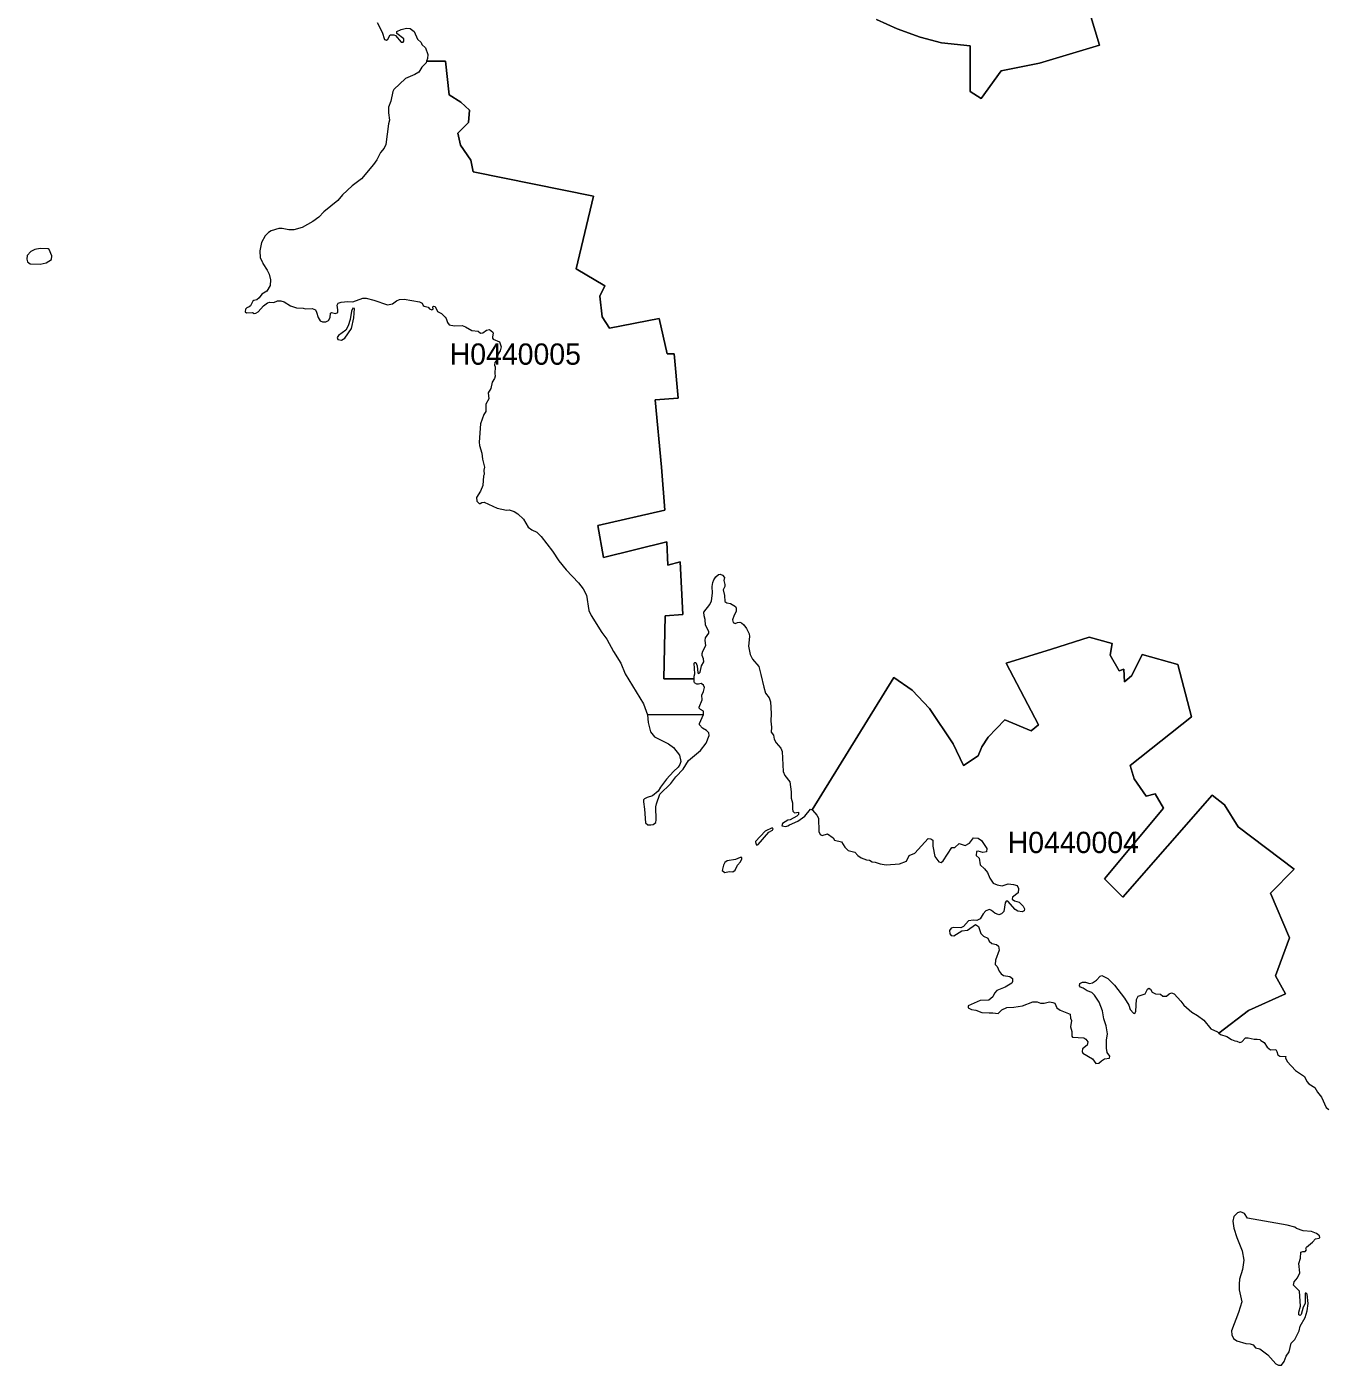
# Model space of a CAD drawing. Extents: x 369010 to 739155, y 6377141 to 6616555.
# Drawn here: x 371724 to 377844, y 6457015 to 6463309 of the extents above; entities that cross this region are included whole.
import ezdxf
from ezdxf.enums import TextEntityAlignment as Align

# ---------------------------------------------------------------- set-up
doc = ezdxf.new("R2010")
doc.units = 0
doc.header["$LTSCALE"] = 40
doc.layers.add('1', color=7, linetype='Continuous', lineweight=13)
doc.layers.add('2', color=7, linetype='Continuous')

msp = doc.modelspace()

# ---------------------------------------------------------------- linework, layer by layer
at = {"layer": '1'}
for points in [[(375720.07, 6463343.08), (375816.39, 6463298.89), (375925.13, 6463259.01), (376025.26, 6463232.53), (376160.97, 6463218.29), (376160.97, 6463004.3), (376211.95, 6462970.7), (376306.28, 6463101.61), (376486.85, 6463137.03), (376767.88, 6463221.93), (376686.94, 6463493.36)], [(376686.94, 6463493.36), (376767.88, 6463221.93), (376486.85, 6463137.03), (376306.28, 6463101.61), (376211.95, 6462970.7), (376160.97, 6463004.3), (376160.97, 6463218.29), (376025.26, 6463232.53), (375925.13, 6463259.01), (375816.39, 6463298.89), (375720.07, 6463343.08)], [(373372.23, 6463328.68), (373395.07, 6463282.51), (373406.65, 6463248.08), (373415.59, 6463246.43), (373421.88, 6463250.4), (373433.14, 6463270.92), (373450.18, 6463271.25), (373458.13, 6463266.95), (373483.95, 6463235.84), (373494.37, 6463235.51), (373496.52, 6463240.8), (373497.85, 6463252.06), (373464.08, 6463276.88), (373464.08, 6463285.82), (373484.61, 6463295.42), (373510.43, 6463301.54), (373527.47, 6463300.05), (373545.68, 6463287.14), (373561.9, 6463249.74), (373578.78, 6463234.51), (373582.42, 6463224.58), (373598.64, 6463209.19), (373609.4, 6463178.74), (373608.4, 6463160.2), (373604.27, 6463147.62), (373693.8, 6463147.13), (373710.69, 6462988.41), (373765.3, 6462954.81), (373806.68, 6462916.58), (373801.05, 6462858.16), (373751.9, 6462808.67), (373763.32, 6462752.07), (373812.31, 6462681.23), (373823.56, 6462626.45), (374389.58, 6462511.43), (374307.99, 6462170.65), (374441.88, 6462091.05), (374419.21, 6462041.56), (374430.63, 6461944.24), (374464.56, 6461891.12), (374698.41, 6461937.13), (374736.15, 6461770.8), (374768.26, 6461770.8), (374787.12, 6461562.09), (374679.55, 6461554.98), (374709.67, 6461237.54), (374724.89, 6461035.96), (374409.77, 6460963.3), (374436.26, 6460813.02), (374734.33, 6460887.33), (374737.97, 6460777.61), (374796.72, 6460792.34), (374809.3, 6460544.74), (374726.88, 6460538.45), (374719.27, 6460242.86), (374861.77, 6460242.2), (374861.77, 6460255.27), (374865.41, 6460265.21), (374862.76, 6460315.68), (374866.07, 6460319.66)], [(373604.27, 6463147.62), (373601.62, 6463139.35), (373581.76, 6463118.66), (373568.19, 6463094.83), (373548.66, 6463083.57), (373505.79, 6463064.71), (373450.84, 6463013.56), (373446.21, 6463004.3), (373435.45, 6462958.12), (373425.85, 6462930.32), (373425.19, 6462903.17), (373429.16, 6462868.91), (373425.19, 6462851.7), (373413.28, 6462755.71), (373405, 6462738), (373387.46, 6462717.31), (373370.58, 6462683.55), (373355.18, 6462661.04), (373298.91, 6462593.35), (373255.05, 6462560.41), (373209.04, 6462518.71), (373187.36, 6462492.23), (373121.16, 6462438.77), (373097.49, 6462413.28), (373068.7, 6462392.76), (373019.87, 6462365.45), (372980.48, 6462354.2), (372956.65, 6462354.2), (372925.04, 6462360.15), (372909.15, 6462360.82), (372872.74, 6462349.23), (372860.33, 6462340.79), (372845.43, 6462326.23), (372827.56, 6462294.12), (372819.61, 6462255.72), (372821.27, 6462221.46), (372832.52, 6462201.93), (372833.51, 6462195.64), (372854.7, 6462164.2), (372864.63, 6462145), (372870.09, 6462118.02), (372867.94, 6462092.53), (372852.71, 6462065.23), (372829.87, 6462050.66), (372816.96, 6462034.11), (372806.04, 6462025.17), (372791.81, 6462022.2), (372787.5, 6462018.89), (372775.75, 6461996.71), (372770.46, 6461991.58), (372758.87, 6461986.61), (372752.58, 6461980.32), (372751.59, 6461967.74), (372757.22, 6461964.1), (372785.35, 6461965.1), (372793.13, 6461960.79), (372801.41, 6461961.46), (372812.33, 6461968.74), (372837.16, 6461995.72), (372856.35, 6462009.95), (372867.11, 6462014.25), (372886.64, 6462011.6), (372902.53, 6462019.22), (372918.42, 6462019.22), (372934.64, 6462015.91), (372964.59, 6461995.72), (372992.73, 6461986.94), (373024.51, 6461985.95), (373034.6, 6461982.64), (373066.38, 6461983.3), (373081.61, 6461977.01), (373087.23, 6461967.08), (373094.51, 6461940.93), (373104.44, 6461926.37), (373114.54, 6461921.4), (373130.43, 6461920.41), (373143.01, 6461927.69), (373151.61, 6461941.26), (373152.94, 6461962.45), (373156.58, 6461965.76), (373176.44, 6461959.8), (373186.37, 6461965.43), (373187.03, 6461977.68), (373183.06, 6461999.36), (373188.69, 6462008.62), (373202.42, 6462013.59), (373234.2, 6462016.24), (373258.03, 6462014.91), (373304.87, 6462032.13), (373319.43, 6462031.79), (373355.68, 6462023.19), (373420.23, 6462001.67), (373444.56, 6462006.31), (373462.1, 6462019.55), (373476.66, 6462025.51), (373498.51, 6462027.82), (373571.17, 6462014.58), (373583.41, 6462008.62), (373587.39, 6461997.37), (373593.01, 6461994.06)], [(374883.28, 6460216.55), (374875.01, 6460216.55), (374864.75, 6460223.17), (374861.77, 6460229.13), (374861.77, 6460242.2), (374719.27, 6460242.86), (374726.88, 6460538.45), (374809.3, 6460544.74), (374796.72, 6460792.34), (374737.97, 6460777.61), (374734.33, 6460887.33), (374436.26, 6460813.02), (374409.77, 6460963.3), (374724.89, 6461035.96), (374709.67, 6461237.54), (374679.55, 6461554.98), (374787.12, 6461562.09), (374768.26, 6461770.8), (374736.15, 6461770.8), (374698.41, 6461937.13), (374464.56, 6461891.12), (374430.63, 6461944.24), (374419.21, 6462041.56), (374441.88, 6462091.05), (374307.99, 6462170.65), (374389.58, 6462511.43), (373823.56, 6462626.45), (373812.31, 6462681.23), (373763.32, 6462752.07), (373751.9, 6462808.67), (373801.05, 6462858.16), (373806.68, 6462916.58), (373765.3, 6462954.81), (373710.69, 6462988.41), (373693.8, 6463147.13), (373604.27, 6463147.62)], [(373593.01, 6461994.06), (373612.38, 6461990.42), (373618.33, 6461982.31), (373628.6, 6461977.68), (373634.88, 6461980.32), (373633.89, 6461991.74), (373636.54, 6461994.06), (373645.15, 6461993.4), (373655.41, 6461969.4), (373673.61, 6461960.79), (373691.98, 6461943.58), (373696.62, 6461936.63), (373702.25, 6461918.42), (373711.18, 6461907.34), (373735.01, 6461902.37), (373771.26, 6461904.36), (373787.81, 6461898.4), (373817.6, 6461880.86), (373847.06, 6461877.55), (373857.49, 6461868.28), (373868.41, 6461868.94), (373886.29, 6461881.85), (373900.52, 6461885.16), (373916.08, 6461872.25), (373918.06, 6461867.61), (373913.76, 6461851.4), (373914.42, 6461843.78), (373917.4, 6461839.81), (373947.36, 6461826.74), (373954.97, 6461803.23), (373950.67, 6461785.03), (373939.74, 6461767.49), (373935.44, 6461744.81), (373925.34, 6461729.92), (373923.69, 6461717.01), (373926.67, 6461709.39), (373925.68, 6461677.62), (373927.33, 6461665.04), (373924.02, 6461653.95), (373912.77, 6461637.4), (373906.81, 6461607.28), (373894.56, 6461587.75), (373896.88, 6461559.12), (373882.64, 6461533.3), (373882.31, 6461499.7), (373873.71, 6461485.47), (373857.16, 6461441.77), (373850.87, 6461354.55), (373852.85, 6461339.99), (373864.77, 6461303.74), (373866.43, 6461274.61), (373876.69, 6461238.37), (373873.05, 6461223.8), (373875.69, 6461203.28), (373871.39, 6461196.99), (373868.74, 6461151.15), (373857.82, 6461124.34), (373839.45, 6461095.21), (373840.77, 6461077.83), (373850.87, 6461067.24), (373856.49, 6461067.24), (373863.45, 6461072.2), (373875.03, 6461072.86), (373936.43, 6461045.39), (373980.13, 6461035.79), (373992.04, 6461036.45), (374016.37, 6461028.51), (374033.25, 6461018.25), (374060.73, 6460993.26), (374081.25, 6460955.19), (374098.63, 6460942.28), (374122.13, 6460932.35), (374142.98, 6460911.33), (374196.11, 6460843.31), (374225.57, 6460797.96), (374261.15, 6460755.1), (374319.08, 6460693.86), (374340.1, 6460664.9), (374356.65, 6460635.11), (374367.9, 6460563.77), (374377.83, 6460539.94), (374427.98, 6460460.67), (374451.15, 6460428.39), (374483.26, 6460371.46), (374518.18, 6460315.35), (374538.7, 6460265.87), (374624.93, 6460124.36), (374642.47, 6460073.55), (374907.11, 6460074.21), (374906.12, 6460090.76), (374892.88, 6460097.72), (374886.59, 6460104.67), (374886.59, 6460109.3), (374900.49, 6460143.56), (374898.51, 6460165.41), (374907.11, 6460183.28), (374911.25, 6460201.65), (374907.11, 6460212.24), (374895.2, 6460220.52), (374883.28, 6460216.55)], [(374866.07, 6460319.66), (374870.37, 6460318.66), (374876.33, 6460302.77), (374879.31, 6460270.5), (374884.27, 6460267.52), (374890.23, 6460273.15), (374896.85, 6460302.77), (374907.28, 6460322.64), (374907.11, 6460335.88), (374900.49, 6460352.09), (374900.16, 6460360.87), (374903.8, 6460372.78), (374917.21, 6460399.93), (374914.56, 6460423.1), (374915.55, 6460435.01), (374930.78, 6460456.69), (374930.78, 6460465.3), (374915.22, 6460495.42), (374913.9, 6460522.07), (374908.77, 6460539.28), (374907.28, 6460556.16), (374936.08, 6460592.57), (374944.68, 6460609.29), (374948.32, 6460645.7), (374947.66, 6460676.15), (374949.65, 6460695.85), (374954.28, 6460708.09), (374964.21, 6460722.66), (374977.45, 6460733.25), (374985.07, 6460733.91), (374995.49, 6460729.94), (375004.43, 6460719.35), (375002.78, 6460704.45), (375007.08, 6460686.58), (375006.42, 6460676.48), (374999.13, 6460660.93), (375005.75, 6460634.44), (375006.09, 6460606.31), (375015.35, 6460599.52), (375033.23, 6460596.21), (375056.73, 6460581.98), (375060.7, 6460574.37), (375060.04, 6460559.47), (375050.11, 6460541.27), (375042.83, 6460519.58), (375045.81, 6460506.68), (375055.07, 6460502.37), (375066.33, 6460507.01), (375076.76, 6460508.33), (375084.7, 6460505.35), (375096.29, 6460496.08), (375109.19, 6460478.54), (375120.45, 6460453.38), (375123.1, 6460442.13), (375118.46, 6460395.95), (375126.08, 6460356.4), (375137.33, 6460334.22), (375165.96, 6460300.13), (375175.89, 6460262.89), (375189.96, 6460203.97), (375198.07, 6460175.01), (375215.61, 6460153.16), (375221.24, 6460133.63), (375224.55, 6460079.01), (375222.4, 6460043.43), (375226.21, 6460015.79), (375223.89, 6459992.12), (375236.3, 6459977.72), (375238.62, 6459958.86), (375247.89, 6459942.14), (375270.23, 6459916.98), (375276.85, 6459900.77), (375281.15, 6459806.76), (375289.26, 6459787.23), (375312.6, 6459758.27), (375318.89, 6459711.1), (375318.06, 6459680.81), (375324.68, 6459658.8), (375324.68, 6459631.82), (375327, 6459619.41), (375334.61, 6459612.79), (375353.64, 6459615.11), (375352.65, 6459604.18), (375346.03, 6459596.57), (375314.42, 6459579.52), (375303.5, 6459578.53), (375277.51, 6459562.81), (375275.2, 6459551.06), (375293.23, 6459548.08), (375303.66, 6459550.56), (375311.27, 6459556.19), (375350.5, 6459573.4), (375383.27, 6459596.07), (375408.92, 6459629.01), (375417.03, 6459625.7), (375417.2, 6459625.86), (375800.67, 6460247.99), (375887.39, 6460189.74), (375968.49, 6460103.18), (376079.71, 6459936.85)], [(376983.86, 6458760.61), (376993.79, 6458783.78), (377000.41, 6458788.08), (377008.02, 6458783.78), (377015.47, 6458768.72), (377031.19, 6458761.93), (377054.86, 6458759.12), (377066.78, 6458750.18), (377083.82, 6458750.18), (377096.73, 6458761.6), (377107.16, 6458765.74), (377120.4, 6458760.61), (377151.51, 6458726.85), (377164.92, 6458707.32), (377202.82, 6458675.54), (377229.96, 6458659.32), (377258.93, 6458636.98), (377292.03, 6458597.09), (377323.31, 6458581.86), (377330.09, 6458576.24), (377469.28, 6458683.32), (377642.9, 6458760.77), (377596.89, 6458846.5), (377662.42, 6459024.26), (377572.56, 6459233.78), (377683.77, 6459346.99), (377420.29, 6459546.42), (377356.24, 6459650.69), (377297.65, 6459695.04), (376878.93, 6459215.58), (376792.2, 6459302.3), (377069.42, 6459634.8), (377029.87, 6459702), (376988.33, 6459691.4), (376931.72, 6459772.83), (376912.86, 6459834.73), (377201.5, 6460062.96), (377137.61, 6460309.56), (376969.79, 6460357.39), (376920.64, 6460258.25), (376886.71, 6460228.13), (376883.07, 6460288.38), (376860.39, 6460279.44), (376818.85, 6460353.75), (376828.28, 6460408.7), (376720.71, 6460438.65), (376543.45, 6460382.05), (376330.28, 6460316.68), (376481.22, 6460026.55), (376447.29, 6459998.25), (376322.67, 6460049.55), (376245.71, 6459968.62), (376215.59, 6459922.61), (376198.54, 6459880.24), (376128.86, 6459834.23), (376079.71, 6459936.85), (375968.49, 6460103.18), (375887.39, 6460189.74), (375800.67, 6460247.99)], [(376079.71, 6459936.85), (376128.86, 6459834.23), (376198.54, 6459880.24), (376215.59, 6459922.61), (376245.71, 6459968.62), (376322.67, 6460049.55), (376447.29, 6459998.25), (376481.22, 6460026.55), (376330.28, 6460316.68), (376543.45, 6460382.05), (376720.71, 6460438.65), (376828.28, 6460408.7), (376818.85, 6460353.75), (376860.39, 6460279.44), (376883.07, 6460288.38), (376886.71, 6460228.13), (376920.64, 6460258.25), (376969.79, 6460357.39), (377137.61, 6460309.56), (377201.5, 6460062.96), (376912.86, 6459834.73), (376931.72, 6459772.83), (376988.33, 6459691.4), (377029.87, 6459702), (377069.42, 6459634.8), (376792.2, 6459302.3), (376878.93, 6459215.58), (377297.65, 6459695.04), (377356.24, 6459650.69), (377420.29, 6459546.42), (377683.77, 6459346.99), (377572.56, 6459233.78), (377662.42, 6459024.26), (377596.89, 6458846.5), (377642.9, 6458760.77), (377469.28, 6458683.32), (377330.09, 6458576.24), (377337.21, 6458570.44), (377366.67, 6458560.02), (377389.01, 6458547.11), (377404.57, 6458539.5), (377415, 6458539), (377429.06, 6458532.87), (377437.17, 6458534.86), (377455.21, 6458554.22), (377467.63, 6458554.72), (377495.6, 6458547.6), (377509.33, 6458548.1), (377523.24, 6458545.78), (377527.54, 6458540.98), (377543.1, 6458531.88), (377556.5, 6458511.03), (377573.38, 6458498.28), (377597.55, 6458498.62), (377603.17, 6458490.67), (377607.48, 6458474.45), (377617.08, 6458467.34), (377644.55, 6458466.34), (377642.73, 6458459.72), (377651.5, 6458443.17), (377689.57, 6458400.14), (377732.1, 6458371.67), (377743.69, 6458348.5), (377753.45, 6458337.41), (377781.59, 6458321.03), (377794, 6458298.19), (377813.2, 6458275.68), (377835.05, 6458226.69), (377846.8, 6458217.26)], [(375800.67, 6460247.99), (375417.2, 6459625.86), (375417.03, 6459625.7), (375418.52, 6459625.2), (375439.87, 6459600.87), (375446.49, 6459587.63), (375448.48, 6459523.91), (375455.1, 6459510.67), (375464.53, 6459505.87), (375488.86, 6459513.49), (375515.51, 6459494.95), (375522.95, 6459483.03), (375555.89, 6459475.92), (375571.45, 6459451.59), (375587.17, 6459435.53), (375617.62, 6459427.42), (375631.86, 6459412.2), (375648.08, 6459400.28), (375672.24, 6459390.85), (375686.97, 6459390.35), (375699.88, 6459381.74), (375713.12, 6459379.92), (375737.78, 6459371.81), (375764.92, 6459368.5), (375827.65, 6459371.81), (375861.41, 6459385.05), (375873.82, 6459411.7), (375899.81, 6459422.62), (375963.03, 6459491.97), (375975.44, 6459490.15), (375984.55, 6459483.53), (375984.55, 6459454.9), (375994.48, 6459407.4), (376013.01, 6459381.25), (376023.94, 6459378.43), (376033.87, 6459386.05), (376073.75, 6459449.27), (376088.15, 6459449.77), (376109, 6459467.81), (376136.97, 6459458.21), (376157.5, 6459470.12), (376176.53, 6459494.45), (376197.88, 6459493.46), (376214.43, 6459481.54), (376238.76, 6459443.97), (376237.27, 6459428.42), (376220.72, 6459425.93), (376198.71, 6459432.22), (376189.77, 6459430.24), (376189.27, 6459411.2), (376202.51, 6459398.96), (376206.82, 6459367.02), (376228.33, 6459349.47), (376241.57, 6459331.93), (376252.99, 6459305.78), (376268.72, 6459281.45), (376288.08, 6459273.01), (376310.42, 6459269.2), (376339.39, 6459277.64), (376364.21, 6459275.33), (376381.26, 6459270.53), (376387.88, 6459256.79), (376385.56, 6459235.94), (376359.91, 6459215.41), (376358.42, 6459206.81), (376368.85, 6459199.19), (376390.69, 6459192.08), (376409.23, 6459173.54), (376415.52, 6459160.8), (376415.02, 6459151.2), (376405.42, 6459147.06), (376384.07, 6459149.38), (376371.33, 6459156.99), (376337.57, 6459196.88), (376329.46, 6459197.37), (376324.66, 6459189.26), (376318.53, 6459148.88), (376307.61, 6459136.96), (376294.7, 6459132.66), (376277.16, 6459140.27), (376261.43, 6459153.68), (376251.5, 6459156.99), (376233.46, 6459152.19), (376221.05, 6459137.46), (376207.81, 6459114.12), (376191.59, 6459106.18), (376175.7, 6459107.01), (376152.04, 6459105.19), (376129.2, 6459077.55), (376116.29, 6459071.92), (376082.19, 6459073.74), (376071.6, 6459070.43), (376063.66, 6459059.01), (376065.48, 6459042.96), (376071.6, 6459034.85), (376083.52, 6459033.36), (376120.59, 6459056.7), (376148.23, 6459060.01), (376184.81, 6459087.15), (376199.04, 6459077.55)], [(376199.04, 6459077.55), (376210.95, 6459045.28), (376222.71, 6459032.03), (376242.73, 6459023.43), (376250.34, 6459008.7), (376262.26, 6458997.78), (376284.6, 6458992.98), (376294.04, 6458984.87), (376297.18, 6458965.83), (376279.64, 6458919.33), (376278.65, 6458899.8), (376288.08, 6458889.87), (376297.18, 6458868.02), (376305.62, 6458854.61), (376317.54, 6458847.99), (376346.17, 6458842.37), (376358.92, 6458833.26), (376359.41, 6458819.03), (376355.61, 6458810.92), (376325.15, 6458791.89), (376285.27, 6458777.16), (376275.34, 6458764.91), (376266.73, 6458746.87), (376247.7, 6458731.15), (376206.82, 6458730.16), (376151.7, 6458705), (376151.21, 6458694.9), (376167.43, 6458686.96), (376186.96, 6458683.65), (376214.93, 6458674.05), (376249.19, 6458671.73), (376266.73, 6458672.56), (376291.39, 6458668.42), (376309.93, 6458685.97), (376333.26, 6458696.89), (376366.03, 6458697.88), (376406.41, 6458705), (376454.41, 6458723.04), (376475.76, 6458723.54), (376490.49, 6458717.25), (376508.53, 6458717.25), (376533.36, 6458723.54), (376548.58, 6458720.72), (376558.02, 6458717.74), (376567.95, 6458694.57), (376583.17, 6458683.98), (376630.34, 6458665.94), (376631.67, 6458646.08), (376636.96, 6458635.98), (376632.66, 6458606.52), (376638.29, 6458583.35), (376637.79, 6458561.84), (376642.09, 6458556.71), (376694.39, 6458554.72), (376704.82, 6458548.6), (376712.93, 6458534.86), (376710.61, 6458520.46), (376689.26, 6458502.42), (376687.77, 6458490.17), (376690.42, 6458481.73), (376735.11, 6458455.58), (376751.49, 6458433.41), (376765.56, 6458434.4), (376777.64, 6458445.49), (376792.2, 6458455.25), (376815.38, 6458458.23), (376817.03, 6458467.34), (376803.96, 6458485.87), (376801.14, 6458505.4), (376801.14, 6458543.8), (376806.27, 6458573.26), (376800.48, 6458610.33), (376789.06, 6458644.09), (376782.77, 6458681.66), (376767.54, 6458722.54), (376745.2, 6458755.31), (376731.96, 6458767.23), (376710.11, 6458775.34), (376691.58, 6458787.09), (376679.17, 6458791.89), (376674.03, 6458799.01), (376675.86, 6458809.43), (376688.76, 6458815.72), (376703.49, 6458816.22), (376721.04, 6458809.93), (376735.77, 6458812.91), (376754.97, 6458826.15), (376771.68, 6458844.19), (376780.29, 6458847), (376808.26, 6458833.76), (376839.21, 6458802.32), (376886.87, 6458741.08), (376906.9, 6458707.32), (376913.52, 6458686.96), (376928.75, 6458669.75), (376935.37, 6458669.25), (376939.67, 6458680.17), (376942.48, 6458734.96), (376951.09, 6458750.18), (376983.86, 6458760.61)]]:
    msp.add_lwpolyline(points, dxfattribs=at)
for points in [[(371824.27, 6462264), (371787.36, 6462265.98), (371762.21, 6462261.35), (371743.67, 6462252.41), (371726.13, 6462233.05), (371724.14, 6462216.17), (371727.78, 6462202.6), (371740.69, 6462193.33), (371786.7, 6462192), (371815.67, 6462198.62), (371841.15, 6462213.52), (371842.15, 6462230.73), (371829.57, 6462261.68)], [(373250.92, 6461890.29), (373262.34, 6461939.94), (373264.98, 6461983.3), (373258.03, 6461984.96), (373250.42, 6461971.05), (373244.13, 6461932), (373234.86, 6461902.04), (373224.27, 6461882.51), (373190.67, 6461856.69), (373183.39, 6461846.76), (373186.7, 6461837.82), (373204.41, 6461835.51), (373219.3, 6461845.11)], [(374907.11, 6460074.21), (374642.47, 6460073.55), (374645.45, 6460037.14), (374657.04, 6459993.61), (374676.4, 6459970.11), (374741.94, 6459936.51), (374765.94, 6459918.97), (374793.41, 6459883.22), (374799.7, 6459854.26), (374795.07, 6459840.03), (374787.12, 6459827.45), (374764.62, 6459806.92), (374731.68, 6459770.02), (374704.21, 6459732.61), (374693.95, 6459714.74), (374666.47, 6459692.73), (374641.48, 6459685.11), (374629.56, 6459678.82), (374624.27, 6459673.2), (374623.61, 6459664.59), (374629.56, 6459628.84), (374633.21, 6459564.79), (374644.46, 6459555.86), (374659.35, 6459555.19), (374669.45, 6459557.51), (374683.02, 6459567.44), (374684.35, 6459580.02), (374682.03, 6459640.1), (374684.68, 6459654.99), (374701.56, 6459700.67), (374753.03, 6459750.82), (374776.2, 6459780.94), (374810.96, 6459817.85), (374835.29, 6459858.56), (374892.22, 6459906.06), (374919.2, 6459940.16), (374932.77, 6459975.74), (374932.11, 6459988.98), (374920.19, 6460000.23), (374901.82, 6460010.16), (374887.92, 6460026.38), (374887.92, 6460032.67)], [(375228.69, 6459541.46), (375196.75, 6459526.73), (375151.23, 6459477.74), (375151.73, 6459465.99), (375157.36, 6459460.19), (375163.48, 6459463.01), (375213.96, 6459520.6), (375231.5, 6459531.53), (375234.32, 6459536.66)], [(375056.4, 6459392.67), (375017.34, 6459386.05), (375006.09, 6459378.93), (374999.8, 6459366.68), (374994.83, 6459341.86), (375006.42, 6459331.27), (375027.27, 6459335.9), (375044.48, 6459334.58), (375054.74, 6459343.18), (375066, 6459366.68), (375079.73, 6459382.41), (375087.35, 6459395.98), (375086.02, 6459402.6), (375078.08, 6459402.27)], [(377610.13, 6457014.71), (377624.52, 6457015.04), (377636.28, 6457032.08), (377646.21, 6457056.91), (377659.94, 6457077.76), (377670.37, 6457118.31), (377686.59, 6457136.19), (377708.1, 6457176.4), (377711.41, 6457198.91), (377734.92, 6457238.8), (377745.18, 6457270.74), (377749.15, 6457304.5), (377744.85, 6457349.52), (377740.21, 6457353.82), (377735.74, 6457352.83), (377735.08, 6457304.84), (377725.98, 6457287.46), (377717.37, 6457253.53), (377712.57, 6457247.9), (377706.61, 6457252.2), (377706.28, 6457263.96), (377714.23, 6457292.75), (377708.77, 6457362.6), (377680.63, 6457391.23), (377684.27, 6457406.29), (377700.33, 6457425.65), (377709.92, 6457449.15), (377706.28, 6457492.52), (377713.9, 6457517.67), (377716.05, 6457546.47), (377724.65, 6457550.28), (377735.91, 6457549.28), (377742.03, 6457557.89), (377739.55, 6457563.02), (377741.37, 6457569.97), (377769.84, 6457592.81), (377784.24, 6457609.53), (377800.79, 6457611.68), (377804.1, 6457615.98), (377802.44, 6457623.43), (377789.04, 6457633.69), (377765.2, 6457642.79), (377726.47, 6457646.44), (377695.53, 6457657.86), (377687.75, 6457664.31), (377650.84, 6457673.41), (377464.15, 6457706.84), (377450.08, 6457728.69), (377432.37, 6457735.48), (377416.82, 6457731.67), (377400.6, 6457714.62), (377395.63, 6457691.78), (377400.27, 6457658.85), (377413.67, 6457615.65), (377440.15, 6457551.93), (377446.94, 6457508.9), (377441.31, 6457465.37), (377427.24, 6457419.7), (377425.09, 6457395.86), (377426.08, 6457369.71), (377437.5, 6457312.28), (377422.44, 6457262.96), (377388.52, 6457175.74), (377390.17, 6457156.87), (377399.27, 6457140.82), (377414.33, 6457129.4), (377456.21, 6457116.66), (377477.06, 6457115.66), (377490.47, 6457109.87), (377501.55, 6457097.13), (377522.24, 6457092.16), (377560.81, 6457063.36), (377597.71, 6457020.66)]]:
    msp.add_lwpolyline(points, close=True, dxfattribs=at)

# ---------------------------------------------------------------- texts
at = {"layer": '2'}
for s, p in [('H0440005', (374021.53, 6461719.41)), ('H0440004', (376645.4, 6459423.16))]:
    msp.add_text(s, height=100, dxfattribs=at).set_placement(p, align=Align.CENTER)

doc.saveas('drawing.dxf')
